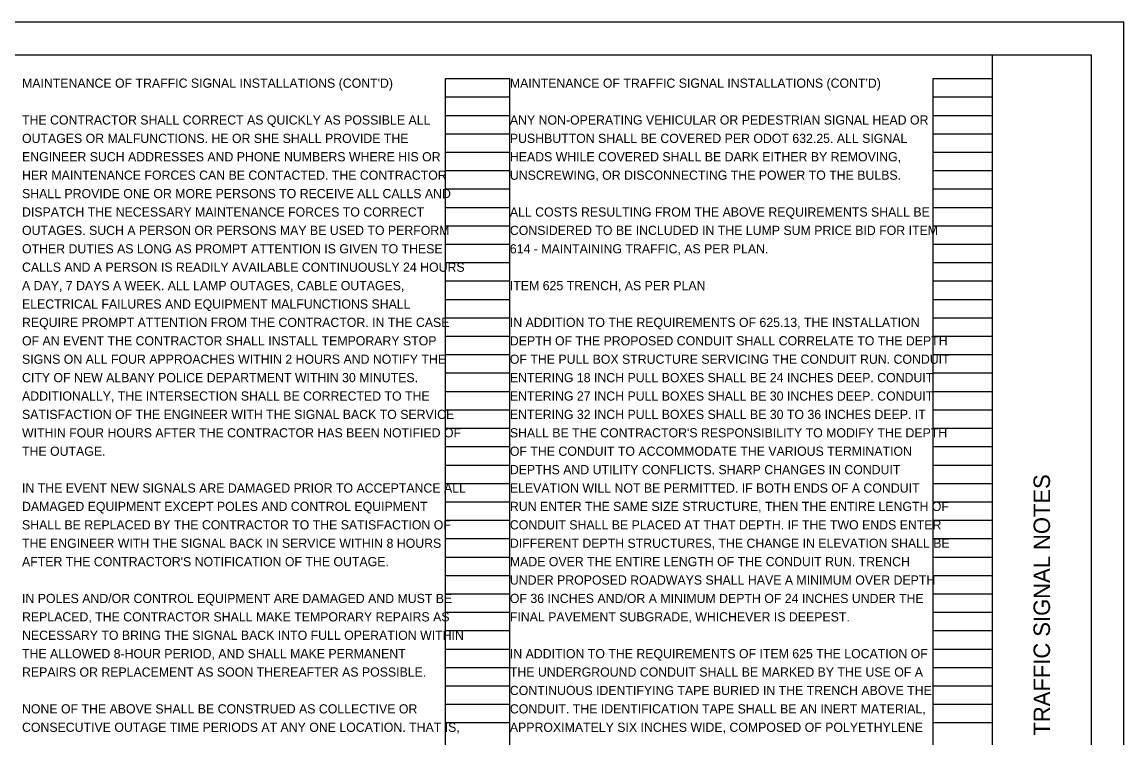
# Model space of a CAD drawing. Extents: x 0 to 34, y 0 to 22.
# Drawn here: x 17.24 to 34, y 11.11 to 22 of the extents above; entities that cross this region are included whole.
import ezdxf

# ---------------------------------------------------------------- set-up
doc = ezdxf.new("R2010")
doc.units = 0
for name, color, linetype in [('SH_Border', 7, 'Continuous'), ('SH_Cut_Line', 7, 'Continuous'), ('SH_Data', 7, 'Continuous'), ('SH_Text', 7, 'Continuous')]:
    doc.layers.add(name, color=color, linetype=linetype)

msp = doc.modelspace()

# ---------------------------------------------------------------- linework, layer by layer
at = {"layer": 'SH_Border'}
msp.add_line((32, 0.5), (32, 21.5), dxfattribs=at)
msp.add_lwpolyline([(1.5, 21.5), (33.5, 21.5), (33.5, 0.5), (1.5, 0.5)], close=True, dxfattribs=at)
at = {"layer": 'SH_Cut_Line'}
msp.add_lwpolyline([(0, 0), (34, 0), (34, 22), (0, 22)], close=True, dxfattribs=at)
at = {"layer": 'SH_Data'}
for p, q in [((23.68, 0.98), (23.68, 21.14)), ((23.68, 21.14), (24.66, 21.14)), ((24.66, 0.98), (24.66, 21.14)), ((31.1, 0.98), (31.1, 21.14)), ((31.1, 21.14), (32, 21.14)), ((32, 0.98), (32, 21.14)), ((23.68, 20.86), (24.66, 20.86)), ((31.1, 20.86), (32, 20.86)), ((23.68, 20.58), (24.66, 20.58)), ((31.1, 20.58), (32, 20.58)), ((23.68, 20.3), (24.66, 20.3)), ((31.1, 20.3), (32, 20.3)), ((23.68, 20.02), (24.66, 20.02)), ((31.1, 20.02), (32, 20.02)), ((23.68, 19.74), (24.66, 19.74)), ((31.1, 19.74), (32, 19.74)), ((23.68, 19.46), (24.66, 19.46)), ((31.1, 19.46), (32, 19.46)), ((23.68, 19.18), (24.66, 19.18)), ((31.1, 19.18), (32, 19.18)), ((23.68, 18.9), (24.66, 18.9)), ((31.1, 18.9), (32, 18.9)), ((23.68, 18.62), (24.66, 18.62)), ((31.1, 18.62), (32, 18.62)), ((23.68, 18.34), (24.66, 18.34)), ((31.1, 18.34), (32, 18.34)), ((23.68, 18.06), (24.66, 18.06)), ((31.1, 18.06), (32, 18.06)), ((23.68, 17.78), (24.66, 17.78)), ((31.1, 17.78), (32, 17.78)), ((23.68, 17.5), (24.66, 17.5)), ((31.1, 17.5), (32, 17.5)), ((23.68, 17.22), (24.66, 17.22)), ((31.1, 17.22), (32, 17.22)), ((23.68, 16.94), (24.66, 16.94)), ((31.1, 16.94), (32, 16.94)), ((23.68, 16.66), (24.66, 16.66)), ((31.1, 16.66), (32, 16.66)), ((23.68, 16.38), (24.66, 16.38)), ((31.1, 16.38), (32, 16.38)), ((23.68, 16.1), (24.66, 16.1)), ((31.1, 16.1), (32, 16.1)), ((23.68, 15.82), (24.66, 15.82)), ((31.1, 15.82), (32, 15.82)), ((23.68, 15.54), (24.66, 15.54)), ((31.1, 15.54), (32, 15.54)), ((23.68, 15.26), (24.66, 15.26)), ((31.1, 15.26), (32, 15.26)), ((23.68, 14.98), (24.66, 14.98)), ((31.1, 14.98), (32, 14.98)), ((23.68, 14.7), (24.66, 14.7)), ((31.1, 14.7), (32, 14.7)), ((23.68, 14.42), (24.66, 14.42)), ((31.1, 14.42), (32, 14.42)), ((23.68, 14.14), (24.66, 14.14)), ((31.1, 14.14), (32, 14.14)), ((23.68, 13.86), (24.66, 13.86)), ((31.1, 13.86), (32, 13.86)), ((23.68, 13.58), (24.66, 13.58)), ((31.1, 13.58), (32, 13.58)), ((23.68, 13.3), (24.66, 13.3)), ((31.1, 13.3), (32, 13.3)), ((23.68, 13.02), (24.66, 13.02)), ((31.1, 13.02), (32, 13.02)), ((23.68, 12.74), (24.66, 12.74)), ((31.1, 12.74), (32, 12.74)), ((23.68, 12.46), (24.66, 12.46)), ((31.1, 12.46), (32, 12.46)), ((23.68, 12.18), (24.66, 12.18)), ((31.1, 12.18), (32, 12.18)), ((23.68, 11.9), (24.66, 11.9)), ((31.1, 11.9), (32, 11.9)), ((23.68, 11.62), (24.66, 11.62)), ((31.1, 11.62), (32, 11.62)), ((23.68, 11.34), (24.66, 11.34)), ((31.1, 11.34), (32, 11.34))]:
    msp.add_line(p, q, dxfattribs=at)

# ---------------------------------------------------------------- texts
msp.add_text('TRAFFIC SIGNAL NOTES', height=0.25, rotation=90, dxfattribs=at).set_placement((32.875, 11.144))
at = {"layer": 'SH_Text'}
for s, p in [("MAINTENANCE OF TRAFFIC SIGNAL INSTALLATIONS (CONT'D)", (17.24, 21)), ("MAINTENANCE OF TRAFFIC SIGNAL INSTALLATIONS (CONT'D)", (24.66, 21)), ('THE CONTRACTOR SHALL CORRECT AS QUICKLY AS POSSIBLE ALL ', (17.24, 20.44)), ('ANY NON-OPERATING VEHICULAR OR PEDESTRIAN SIGNAL HEAD OR ', (24.66, 20.44)), ('OUTAGES OR MALFUNCTIONS. HE OR SHE SHALL PROVIDE THE ', (17.24, 20.16)), ('PUSHBUTTON SHALL BE COVERED PER ODOT 632.25. ALL SIGNAL ', (24.66, 20.16)), ('ENGINEER SUCH ADDRESSES AND PHONE NUMBERS WHERE HIS OR ', (17.24, 19.88)), ('HEADS WHILE COVERED SHALL BE DARK EITHER BY REMOVING, ', (24.66, 19.88)), ('HER MAINTENANCE FORCES CAN BE CONTACTED. THE CONTRACTOR ', (17.24, 19.6)), ('UNSCREWING, OR DISCONNECTING THE POWER TO THE BULBS.', (24.66, 19.6)), ('SHALL PROVIDE ONE OR MORE PERSONS TO RECEIVE ALL CALLS AND ', (17.24, 19.32)), ('DISPATCH THE NECESSARY MAINTENANCE FORCES TO CORRECT ', (17.24, 19.04)), ('ALL COSTS RESULTING FROM THE ABOVE REQUIREMENTS SHALL BE ', (24.66, 19.04)), ('OUTAGES. SUCH A PERSON OR PERSONS MAY BE USED TO PERFORM ', (17.24, 18.76)), ('CONSIDERED TO BE INCLUDED IN THE LUMP SUM PRICE BID FOR ITEM ', (24.66, 18.76)), ('OTHER DUTIES AS LONG AS PROMPT ATTENTION IS GIVEN TO THESE ', (17.24, 18.48)), ('614 - MAINTAINING TRAFFIC, AS PER PLAN.', (24.66, 18.48)), ('CALLS AND A PERSON IS READILY AVAILABLE CONTINUOUSLY 24 HOURS ', (17.24, 18.2)), ('A DAY, 7 DAYS A WEEK. ALL LAMP OUTAGES, CABLE OUTAGES, ', (17.24, 17.92)), ('ITEM 625 TRENCH, AS PER PLAN', (24.66, 17.92)), ('ELECTRICAL FAILURES AND EQUIPMENT MALFUNCTIONS SHALL ', (17.24, 17.64)), ('REQUIRE PROMPT ATTENTION FROM THE CONTRACTOR. IN THE CASE ', (17.24, 17.36)), ('IN ADDITION TO THE REQUIREMENTS OF 625.13, THE INSTALLATION ', (24.66, 17.36)), ('OF AN EVENT THE CONTRACTOR SHALL INSTALL TEMPORARY STOP ', (17.24, 17.08)), ('DEPTH OF THE PROPOSED CONDUIT SHALL CORRELATE TO THE DEPTH ', (24.66, 17.08)), ('SIGNS ON ALL FOUR APPROACHES WITHIN 2 HOURS AND NOTIFY THE ', (17.24, 16.8)), ('OF THE PULL BOX STRUCTURE SERVICING THE CONDUIT RUN. CONDUIT ', (24.66, 16.8)), ('CITY OF NEW ALBANY POLICE DEPARTMENT WITHIN 30 MINUTES. ', (17.24, 16.52)), ('ENTERING 18 INCH PULL BOXES SHALL BE 24 INCHES DEEP. CONDUIT ', (24.66, 16.52)), ('ADDITIONALLY, THE INTERSECTION SHALL BE CORRECTED TO THE ', (17.24, 16.24)), ('ENTERING 27 INCH PULL BOXES SHALL BE 30 INCHES DEEP. CONDUIT ', (24.66, 16.24)), ('SATISFACTION OF THE ENGINEER WITH THE SIGNAL BACK TO SERVICE ', (17.24, 15.96)), ('ENTERING 32 INCH PULL BOXES SHALL BE 30 TO 36 INCHES DEEP. IT ', (24.66, 15.96)), ('WITHIN FOUR HOURS AFTER THE CONTRACTOR HAS BEEN NOTIFIED OF ', (17.24, 15.68)), ("SHALL BE THE CONTRACTOR'S RESPONSIBILITY TO MODIFY THE DEPTH ", (24.66, 15.68)), ('THE OUTAGE.', (17.24, 15.4)), ('OF THE CONDUIT TO ACCOMMODATE THE VARIOUS TERMINATION ', (24.66, 15.4)), ('DEPTHS AND UTILITY CONFLICTS. SHARP CHANGES IN CONDUIT ', (24.66, 15.12)), ('IN THE EVENT NEW SIGNALS ARE DAMAGED PRIOR TO ACCEPTANCE ALL ', (17.24, 14.84)), ('ELEVATION WILL NOT BE PERMITTED. IF BOTH ENDS OF A CONDUIT ', (24.66, 14.84)), ('DAMAGED EQUIPMENT EXCEPT POLES AND CONTROL EQUIPMENT ', (17.24, 14.56)), ('RUN ENTER THE SAME SIZE STRUCTURE, THEN THE ENTIRE LENGTH OF ', (24.66, 14.56)), ('SHALL BE REPLACED BY THE CONTRACTOR TO THE SATISFACTION OF ', (17.24, 14.28)), ('CONDUIT SHALL BE PLACED AT THAT DEPTH. IF THE TWO ENDS ENTER ', (24.66, 14.28)), ('THE ENGINEER WITH THE SIGNAL BACK IN SERVICE WITHIN 8 HOURS ', (17.24, 14)), ('DIFFERENT DEPTH STRUCTURES, THE CHANGE IN ELEVATION SHALL BE ', (24.66, 14)), ("AFTER THE CONTRACTOR'S NOTIFICATION OF THE OUTAGE.", (17.24, 13.72)), ('MADE OVER THE ENTIRE LENGTH OF THE CONDUIT RUN. TRENCH ', (24.66, 13.72)), ('UNDER PROPOSED ROADWAYS SHALL HAVE A MINIMUM OVER DEPTH ', (24.66, 13.44)), ('IN POLES AND/OR CONTROL EQUIPMENT ARE DAMAGED AND MUST BE ', (17.24, 13.16)), ('OF 36 INCHES AND/OR A MINIMUM DEPTH OF 24 INCHES UNDER THE ', (24.66, 13.16)), ('REPLACED, THE CONTRACTOR SHALL MAKE TEMPORARY REPAIRS AS ', (17.24, 12.88)), ('FINAL PAVEMENT SUBGRADE, WHICHEVER IS DEEPEST.', (24.66, 12.88)), ('NECESSARY TO BRING THE SIGNAL BACK INTO FULL OPERATION WITHIN ', (17.24, 12.6)), ('THE ALLOWED 8-HOUR PERIOD, AND SHALL MAKE PERMANENT ', (17.24, 12.32)), ('IN ADDITION TO THE REQUIREMENTS OF ITEM 625 THE LOCATION OF ', (24.66, 12.32)), ('REPAIRS OR REPLACEMENT AS SOON THEREAFTER AS POSSIBLE.', (17.24, 12.04)), ('THE UNDERGROUND CONDUIT SHALL BE MARKED BY THE USE OF A ', (24.66, 12.04)), ('CONTINUOUS IDENTIFYING TAPE BURIED IN THE TRENCH ABOVE THE ', (24.66, 11.76)), ('NONE OF THE ABOVE SHALL BE CONSTRUED AS COLLECTIVE OR ', (17.24, 11.48)), ('CONDUIT. THE IDENTIFICATION TAPE SHALL BE AN INERT MATERIAL, ', (24.66, 11.48)), ('CONSECUTIVE OUTAGE TIME PERIODS AT ANY ONE LOCATION. THAT IS, ', (17.24, 11.2)), ('APPROXIMATELY SIX INCHES WIDE, COMPOSED OF POLYETHYLENE ', (24.66, 11.2))]:
    msp.add_text(s, height=0.14, dxfattribs=at).set_placement(p)

doc.saveas('drawing.dxf')
